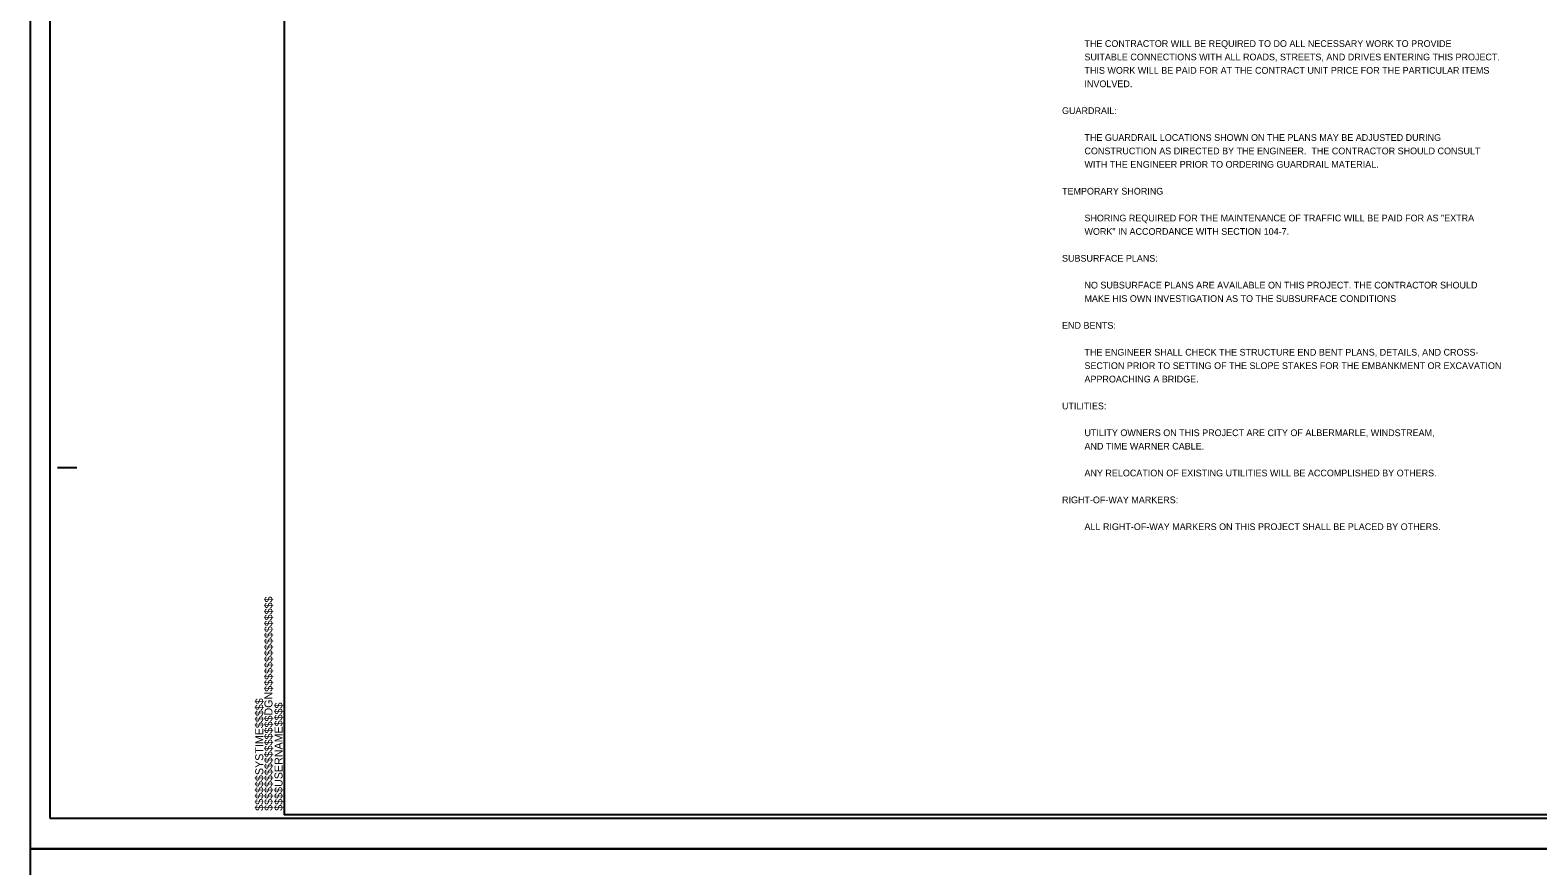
# Model space of a CAD drawing. Extents: x 1664524 to 1666208, y 587901 to 592296.
# Drawn here: x 1664524 to 1665512, y 590090 to 590638 of the extents above; entities that cross this region are included whole.
import ezdxf

# ---------------------------------------------------------------- set-up
doc = ezdxf.new("R2010")
doc.units = 0
for name, color, linetype in [('Old_Level_11', 7, 'Continuous'), ('Prop Horizontal Alignment Tick Large', 7, 'Continuous'), ('Prop Horizontal Alignment Tick Small', 7, 'Continuous'), ('Sheet Cutting Line CELL', 7, 'Continuous'), ('Sheet Plan CELL', 7, 'Continuous')]:
    doc.layers.add(name, color=color, linetype=linetype)

msp = doc.modelspace()

# ---------------------------------------------------------------- linework, layer by layer
at = {"layer": 'Prop Horizontal Alignment Tick Large'}
msp.add_lwpolyline([(1664536.76, 590121.35), (1666202.76, 590121.35), (1666202.76, 591176.35), (1664536.76, 591176.35)], close=True, dxfattribs=at)
at = {"layer": 'Prop Horizontal Alignment Tick Small'}
for points in [[(1664523.76, 590101.35), (1666207.26, 590101.35), (1666207.26, 591196.35), (1664523.76, 591196.35)], [(1664523.76, 589001.35), (1666207.76, 589001.35), (1666207.76, 590101.35), (1664523.76, 590101.35)]]:
    msp.add_lwpolyline(points, close=True, dxfattribs=at)
at = {"layer": 'Sheet Cutting Line CELL'}
for p, q in [((1664523.76, 591196.35), (1664523.76, 590101.35)), ((1666207.76, 590101.35), (1664523.76, 590101.35)), ((1664523.76, 590101.35), (1664523.76, 589001.35)), ((1664523.76, 590101.35), (1666207.26, 590101.35))]:
    msp.add_line(p, q, dxfattribs=at)
at = {"layer": 'Sheet Plan CELL'}
for p, q in [((1664541.76, 590351.35), (1664554.26, 590351.35)), ((1664690.26, 590123.85), (1664690.26, 590123.85))]:
    msp.add_line(p, q, dxfattribs=at)
msp.add_lwpolyline([(1666190.26, 591173.85), (1664690.26, 591173.85), (1664690.26, 590123.85), (1666190.26, 590123.85)], close=True, dxfattribs=at)

# ---------------------------------------------------------------- texts
at = {"layer": 'Old_Level_11'}
for s, p in [('         THE CONTRACTOR WILL BE REQUIRED TO DO ALL NECESSARY WORK TO PROVIDE ', (1665200.17, 590627.09)), ('         SUITABLE CONNECTIONS WITH ALL ROADS, STREETS, AND DRIVES ENTERING THIS PROJECT.  ', (1665200.17, 590618.29)), ('         THIS WORK WILL BE PAID FOR AT THE CONTRACT UNIT PRICE FOR THE PARTICULAR ITEMS ', (1665200.17, 590609.49)), ('         INVOLVED.  ', (1665200.17, 590600.69)), ('GUARDRAIL:  ', (1665200.17, 590583.09)), ('         THE GUARDRAIL LOCATIONS SHOWN ON THE PLANS MAY BE ADJUSTED DURING ', (1665200.17, 590565.49)), ('         CONSTRUCTION AS DIRECTED BY THE ENGINEER.  THE CONTRACTOR SHOULD CONSULT', (1665200.17, 590556.69)), ('         WITH THE ENGINEER PRIOR TO ORDERING GUARDRAIL MATERIAL.', (1665200.17, 590547.89)), ('TEMPORARY SHORING', (1665200.17, 590530.29)), ('         SHORING REQUIRED FOR THE MAINTENANCE OF TRAFFIC WILL BE PAID FOR AS "EXTRA', (1665200.17, 590512.69)), ('         WORK" IN ACCORDANCE WITH SECTION 104-7.', (1665200.17, 590503.89)), ('SUBSURFACE PLANS:  ', (1665200.17, 590486.29)), ('         NO SUBSURFACE PLANS ARE AVAILABLE ON THIS PROJECT. THE CONTRACTOR SHOULD ', (1665200.17, 590468.69)), ('         MAKE HIS OWN INVESTIGATION AS TO THE SUBSURFACE CONDITIONS', (1665200.17, 590459.89)), ('END BENTS:  ', (1665200.17, 590442.29)), ('         THE ENGINEER SHALL CHECK THE STRUCTURE END BENT PLANS, DETAILS, AND CROSS-', (1665200.17, 590424.69)), ('         SECTION PRIOR TO SETTING OF THE SLOPE STAKES FOR THE EMBANKMENT OR EXCAVATION ', (1665200.17, 590415.89)), ('         APPROACHING A BRIDGE.  ', (1665200.17, 590407.09)), ('UTILITIES:  ', (1665200.17, 590389.49)), ('         UTILITY OWNERS ON THIS PROJECT ARE CITY OF ALBERMARLE, WINDSTREAM,  ', (1665200.17, 590371.89)), ('         AND TIME WARNER CABLE. ', (1665200.17, 590363.09)), ('         ANY RELOCATION OF EXISTING UTILITIES WILL BE ACCOMPLISHED BY OTHERS. ', (1665200.17, 590345.49)), ('RIGHT-OF-WAY MARKERS:  ', (1665200.17, 590327.89)), ('         ALL RIGHT-OF-WAY MARKERS ON THIS PROJECT SHALL BE PLACED BY OTHERS. ', (1665200.17, 590310.29))]:
    msp.add_text(s, height=4.4, rotation=360, dxfattribs=at).set_placement(p)
at = {"layer": 'Sheet Plan CELL'}
for s, p in [('$$$$$$$$$$$$$$$$DGN$$$$$$$$$$$$$$$$', (1664682.61, 590126.21)), ('$$$$$$SYSTIME$$$$$', (1664676.56, 590126.21)), ('$$$$USERNAME$$$$', (1664689.19, 590126.22))]:
    msp.add_text(s, height=5.25, rotation=90, dxfattribs=at).set_placement(p)

doc.saveas('drawing.dxf')
